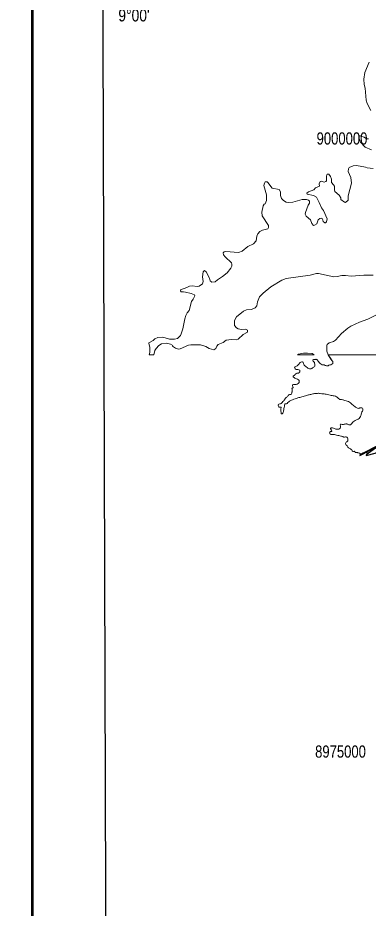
# Model space of a CAD drawing. Extents: x -1643653 to 4543381, y 1624270 to 13878484.
# Drawn here: x 559607 to 573973, y 8968607 to 9005087 of the extents above; entities that cross this region are included whole.
import ezdxf
from ezdxf.enums import TextEntityAlignment as Align

# ---------------------------------------------------------------- set-up
doc = ezdxf.new("R2010")
doc.units = 0
doc.header["$LTSCALE"] = 200
for name, color, linetype, lineweight in [('1', 7, 'Continuous', 13), ('25', 7, 'Continuous', 13), ('3', 7, 'Continuous', 13)]:
    doc.layers.add(name, color=color, linetype=linetype, lineweight=lineweight)
doc.layers.add('46', color=7, linetype='Continuous')
doc.layers.add('47', color=7, linetype='Continuous')

msp = doc.modelspace()

# ---------------------------------------------------------------- linework, layer by layer
at = {"layer": '1', "lineweight": 25}
msp.add_spline([(814781, 9009175.5), (814787.2, 9009173.4), (814796.9, 9009173.4), (814799.4, 9009172.4), (814805.1, 9009174.5), (814805.6, 9009176.5), (814811.7, 9009179.5), (814811.7, 9009179.5), (814801.5, 9009181), (814790.7, 9009181.5), (814784.1, 9009183.1), (814777.4, 9009185.1), (814778.4, 9009175.5)], degree=3, dxfattribs=at)
at = {"layer": '25'}
for p, q in [((571078.4, 8991274.5), (571756.4, 8991274.5)), ((572449.1, 8991100.5), (572334.3, 8991274.5))]:
    msp.add_line(p, q, dxfattribs=at)
at = {"layer": '25', "lineweight": 25}
for p, q in [((577877.7, 8989395.6), (573616.6, 8987168.4)), ((573625.3, 8987151.7), (577886.4, 8989378.8))]:
    msp.add_line(p, q, dxfattribs=at)
at = {"layer": '25'}
for points in [[(574014.7, 9003264.2), (573829.1, 9002845.8), (573792.1, 9002568.4), (573811.5, 9002356.8), (573854.8, 9002205), (573887.2, 9001708), (573923.9, 9001569.9), (574075.2, 9001284.5)], [(574014.7, 9003264.2), (573829.1, 9002845.8), (573792.1, 9002568.4), (573811.5, 9002356.8), (573854.8, 9002205), (573887.2, 9001708), (573923.9, 9001569.9), (574075.2, 9001284.5)], [(573989.5, 9000125.8), (573897.6, 9000125.8), (573807.4, 9000194.6), (573651.6, 9000255.2), (573610.4, 9000246.4), (573582.4, 9000173.4), (573662.4, 8999991.6), (573850.3, 8999788.5), (574105.5, 8999671.6)], [(573989.5, 9000125.8), (573897.6, 9000125.8), (573807.4, 9000194.6), (573651.6, 9000255.2), (573610.4, 9000246.4), (573582.4, 9000173.4), (573662.4, 8999991.6), (573850.3, 8999788.5), (574105.5, 8999671.6)], [(574169.9, 8998917.3), (573924.2, 8998943.1), (573861.2, 8998973.3), (573495.9, 8999038.2), (573357.6, 8999025.2), (573195.7, 8998954), (573160.9, 8998904.1), (573154.4, 8998796.3), (573264.6, 8998547.5), (573290.5, 8998318.6), (573147.9, 8997786.5), (573147.7, 8997610.4), (573041.5, 8997523.5), (573000.7, 8997531.6), (572856.3, 8997643.8), (572845.2, 8997713), (572780.5, 8997814.4), (572609.7, 8997966), (572588, 8998037.6), (572585.8, 8998184.3), (572553.4, 8998244.8), (572469.1, 8998340), (572464.8, 8998478.1), (572423.8, 8998581.8), (572354.7, 8998677), (572291.7, 8998674.9), (572271.2, 8998655.2), (572257.2, 8998599.6), (572268, 8998409.4), (572236.1, 8998375.1), (572164.3, 8998348.7), (572065.1, 8998398.3), (572002.4, 8998374.6), (571967.6, 8998284), (571974, 8998195.7), (571816.4, 8998119.6), (571747.1, 8998035.2), (571528.9, 8997959.6), (571454.6, 8997898.7), (571466.8, 8997864.9), (571737.3, 8997804.6), (571855.7, 8997734.5), (571967.5, 8997514.1), (572052.2, 8997299.3), (572136.7, 8997188.2), (572285.2, 8996857.2), (572259.3, 8996727.3), (572229.1, 8996686.3), (572195.3, 8996686.2), (572121.1, 8996746.8), (572103.5, 8996844.1), (572051.6, 8996874.3), (571987.6, 8996870.2), (571987.6, 8996870.2)], [(574169.9, 8998917.3), (573924.2, 8998943.1), (573861.2, 8998973.3), (573495.9, 8999038.2), (573357.6, 8999025.2), (573195.7, 8998954), (573160.9, 8998904.1), (573154.4, 8998796.3), (573264.6, 8998547.5), (573290.5, 8998318.6), (573147.9, 8997786.5), (573147.7, 8997610.4), (573041.5, 8997523.5), (573000.7, 8997531.6), (572856.3, 8997643.8), (572845.2, 8997713), (572780.5, 8997814.4), (572609.7, 8997966), (572588, 8998037.6), (572585.8, 8998184.3), (572553.4, 8998244.8), (572469.1, 8998340), (572464.8, 8998478.1), (572423.8, 8998581.8), (572354.7, 8998677), (572291.7, 8998674.9), (572271.2, 8998655.2), (572257.2, 8998599.6), (572268, 8998409.4), (572236.1, 8998375.1), (572164.3, 8998348.7), (572065.1, 8998398.3), (572002.4, 8998374.6), (571967.6, 8998284), (571974, 8998195.7), (571816.4, 8998119.6), (571747.1, 8998035.2), (571528.9, 8997959.6), (571454.6, 8997898.7), (571466.8, 8997864.9), (571737.3, 8997804.6), (571855.7, 8997734.5), (571967.5, 8997514.1), (572052.2, 8997299.3), (572136.7, 8997188.2), (572285.2, 8996857.2), (572259.3, 8996727.3), (572229.1, 8996686.3), (572195.3, 8996686.2), (572121.1, 8996746.8), (572103.5, 8996844.1), (572051.6, 8996874.3), (571987.6, 8996870.2)], [(571987.6, 8996870.2), (571926.5, 8996807.2), (571865.9, 8996647.3), (571765.8, 8996584.6), (571736.3, 8996582.5), (571667.1, 8996658.1), (571606.5, 8996815.9), (571427, 8996963.1), (571394.8, 8997042.6), (571399.2, 8997108.2), (571513.5, 8997414.5), (571561.1, 8997492.8), (571561.1, 8997570.3), (571528.4, 8997620.1), (571442, 8997643.9), (571269.3, 8997639.5), (570879.9, 8997529.3), (570707.2, 8997522.8), (570605.6, 8997535.8), (570495.4, 8997602.8), (570421.8, 8997687.3), (570378.7, 8997803.8), (570376.4, 8997959.5), (570326.5, 8998050.2), (570039.3, 8998110.8), (569862.2, 8998339.7), (569828.8, 8998363.9), (569747.5, 8998367.9), (569719.3, 8998318.1), (569695.6, 8998210), (569803.5, 8997832.4), (569805.7, 8997600.4), (569753.7, 8997466.5), (569708.6, 8997447), (569671.8, 8997384.4), (569607, 8997125.3), (569624.2, 8996969.4), (569883.5, 8996580.5), (569890, 8996489.7), (569862.1, 8996442.2), (569634.2, 8996387.6), (569524.8, 8996331.6), (569444.9, 8996241), (569401.6, 8996135.2), (569377.7, 8995955.6), (569276.2, 8995821.7), (569042.7, 8995719.9), (568806.8, 8995531.7), (568653.5, 8995475.6), (568134.7, 8995512.3), (568072.2, 8995501.6), (568030.8, 8995462.5), (568041.7, 8995378.5), (568108.6, 8995287.8), (568364, 8995043), (568387.6, 8994997.6), (568385.5, 8994911.7), (568342.3, 8994825.1), (568190.7, 8994643.1), (567996.1, 8994487.5), (567788.8, 8994357.9), (567698, 8994275.9), (567560, 8994252.1), (567499.2, 8994304.1), (567462.2, 8994418.7), (567330.6, 8994677.7), (567263.6, 8994734), (567200.7, 8994675.1), (567183.6, 8994478), (567209.4, 8994288.5), (567174.9, 8994185.2), (567041.5, 8994087.6), (566962.8, 8994081.3), (566755.8, 8994109.3), (566652.7, 8994094.4), (566443.9, 8994001.2), (566287.2, 8993950.5), (566277.5, 8993895.3), (566309.1, 8993863.6), (566406.3, 8993853.8)], [(571987.6, 8996870.2), (571926.5, 8996807.2), (571865.9, 8996647.3), (571765.8, 8996584.6), (571736.3, 8996582.5), (571667.1, 8996658.1), (571606.5, 8996815.9), (571427, 8996963.1), (571394.8, 8997042.6), (571399.2, 8997108.2), (571513.5, 8997414.5), (571561.1, 8997492.8), (571561.1, 8997570.3), (571528.4, 8997620.1), (571442, 8997643.9), (571269.3, 8997639.5), (570879.9, 8997529.3), (570707.2, 8997522.8), (570605.6, 8997535.8), (570495.4, 8997602.8), (570421.8, 8997687.3), (570378.7, 8997803.8), (570376.4, 8997959.5), (570326.5, 8998050.2), (570039.3, 8998110.8), (569862.2, 8998339.7), (569828.8, 8998363.9), (569747.5, 8998367.9), (569719.3, 8998318.1), (569695.6, 8998210), (569803.5, 8997832.4), (569805.7, 8997600.4), (569753.7, 8997466.5), (569708.6, 8997447), (569671.8, 8997384.4), (569607, 8997125.3), (569624.2, 8996969.4), (569883.5, 8996580.5), (569890, 8996489.7), (569862.1, 8996442.2), (569634.2, 8996387.6), (569524.8, 8996331.6), (569444.9, 8996241), (569401.6, 8996135.2), (569377.7, 8995955.6), (569276.2, 8995821.7), (569042.7, 8995719.9), (568806.8, 8995531.7), (568653.5, 8995475.6), (568134.7, 8995512.3), (568072.2, 8995501.6), (568030.8, 8995462.5), (568041.7, 8995378.5), (568108.6, 8995287.8), (568364, 8995043), (568387.6, 8994997.6), (568385.5, 8994911.7), (568342.3, 8994825.1), (568190.7, 8994643.1), (567996.1, 8994487.5), (567788.8, 8994357.9), (567698, 8994275.9), (567560, 8994252.1), (567499.2, 8994304.1), (567462.2, 8994418.7), (567330.6, 8994677.7), (567263.6, 8994734), (567200.7, 8994675.1), (567183.6, 8994478), (567209.4, 8994288.5), (567174.9, 8994185.2), (567041.5, 8994087.6), (566962.8, 8994081.3), (566755.8, 8994109.3), (566652.7, 8994094.4), (566443.9, 8994001.2), (566287.2, 8993950.5), (566277.5, 8993895.3), (566309.1, 8993863.6), (566406.3, 8993853.8)], [(568487.1, 8992684.5), (568569.1, 8992838), (568854.8, 8993074), (568977.6, 8993117), (569194, 8993136.6), (569341.2, 8993199.5), (569413.7, 8993286.4), (569438.4, 8993446), (569516.9, 8993653.7), (569666.9, 8993803.6), (569976.6, 8994064), (570432.9, 8994338.6), (570607.5, 8994403.3), (571593.3, 8994539.5), (571853, 8994615.2), (571939.4, 8994608.7), (572566.4, 8994472.6), (572704.5, 8994483.3), (572894.9, 8994524.4), (573037.9, 8994528.7), (573275.2, 8994507.1), (573798.6, 8994543.9), (574179, 8994537.4)], [(568487.1, 8992684.5), (568569.1, 8992838), (568854.8, 8993074), (568977.6, 8993117), (569194, 8993136.6), (569341.2, 8993199.5), (569413.7, 8993286.4), (569438.4, 8993446), (569516.9, 8993653.7), (569666.9, 8993803.6), (569976.6, 8994064), (570432.9, 8994338.6), (570607.5, 8994403.3), (571593.3, 8994539.5), (571853, 8994615.2), (571939.4, 8994608.7), (572566.4, 8994472.6), (572704.5, 8994483.3), (572894.9, 8994524.4), (573037.9, 8994528.7), (573275.2, 8994507.1), (573798.6, 8994543.9), (574179, 8994537.4)], [(566406.3, 8993853.8), (566487.5, 8993845.6), (566720.4, 8993798.2), (566856.8, 8993741.9), (566861.3, 8993701.1), (566803.3, 8993560.8), (566725.3, 8993467.3), (566628, 8993095.8), (566556.6, 8993002.5), (566500.5, 8992892.5), (566452.8, 8992749.4), (566371.7, 8992344.8), (566307.9, 8992133.6), (566273.3, 8992070.6), (566159, 8991941.3), (566037.8, 8991923.8), (565822.3, 8991921.6), (565557.9, 8992003.8), (565347.2, 8991985.1), (565224.8, 8991932.3), (565151.5, 8991872), (564980.8, 8991770.3), (564976.4, 8991740.3), (564976.4, 8991740.3), (565017.4, 8991591.1), (565017.4, 8991374.7), (564994.9, 8991274.5), (565186.5, 8991274.5)], [(566406.3, 8993853.8), (566487.5, 8993845.6), (566720.4, 8993798.2), (566856.8, 8993741.9), (566861.3, 8993701.1), (566803.3, 8993560.8), (566725.3, 8993467.3), (566628, 8993095.8), (566556.6, 8993002.5), (566500.5, 8992892.5), (566452.8, 8992749.4), (566371.7, 8992344.8), (566307.9, 8992133.6), (566273.3, 8992070.6), (566159, 8991941.3), (566037.8, 8991923.8), (565822.3, 8991921.6), (565557.9, 8992003.8), (565347.2, 8991985.1), (565224.8, 8991932.3), (565151.5, 8991872), (564980.8, 8991770.3), (564976.4, 8991740.3), (564976.4, 8991740.3), (565017.4, 8991591.1), (565017.4, 8991374.7), (564994.9, 8991274.5), (565186.5, 8991274.5)], [(574604.9, 8993095.5), (574470.8, 8992998.2), (573958.5, 8992743.1), (573612.4, 8992613.3), (573265.1, 8992456.7), (573136.5, 8992373), (572873.3, 8992152.9), (572626.3, 8991880.2), (572549.3, 8991828.8), (572375.9, 8991770.2), (572289.7, 8991707.6), (572272.4, 8991674.5), (572272.4, 8991435), (572334.3, 8991274.5), (578446.9, 8991274.5)], [(574604.9, 8993095.5), (574470.8, 8992998.2), (573958.5, 8992743.1), (573612.4, 8992613.3), (573265.1, 8992456.7), (573136.5, 8992373), (572873.3, 8992152.9), (572626.3, 8991880.2), (572549.3, 8991828.8), (572375.9, 8991770.2), (572289.7, 8991707.6), (572272.4, 8991674.5), (572272.4, 8991435), (572334.3, 8991274.5)], [(565186.5, 8991274.5), (565229.4, 8991456.8), (565277, 8991543.6), (565385, 8991662.2), (565495.2, 8991724.9), (565699.6, 8991750.3), (565868.8, 8991714.1), (565962.8, 8991656.3), (565956, 8991638.4), (566069.6, 8991550.2), (566202.1, 8991510.9), (566262.2, 8991518.1), (566602.6, 8991670.9), (566699.3, 8991686), (567101.1, 8991683.8), (567313.2, 8991623.3), (567457.9, 8991543.5), (567647.8, 8991487.2), (567719.8, 8991534.9), (567767.4, 8991634.3), (567827.8, 8991705.4), (568027.3, 8991790.1), (568156.3, 8991874), (568371.7, 8991906.5), (568571.6, 8991889.4), (568638.4, 8991921.7), (568847.5, 8992104.9), (569018.9, 8992209.7), (569025.4, 8992289.9), (568938.9, 8992336.7), (568783.5, 8992319.5), (568643, 8992349.7), (568576.9, 8992385), (568495.8, 8992479.4), (568487.1, 8992684.5)], [(565186.5, 8991274.5), (565229.4, 8991456.8), (565277, 8991543.6), (565385, 8991662.2), (565495.2, 8991724.9), (565699.6, 8991750.3), (565868.8, 8991714.1), (565962.8, 8991656.3), (565956, 8991638.4), (566069.6, 8991550.2), (566202.1, 8991510.9), (566262.2, 8991518.1), (566602.6, 8991670.9), (566699.3, 8991686), (567101.1, 8991683.8), (567313.2, 8991623.3), (567457.9, 8991543.5), (567647.8, 8991487.2), (567719.8, 8991534.9), (567767.4, 8991634.3), (567827.8, 8991705.4), (568027.3, 8991790.1), (568156.3, 8991874), (568371.7, 8991906.5), (568571.6, 8991889.4), (568638.4, 8991921.7), (568847.5, 8992104.9), (569018.9, 8992209.7), (569025.4, 8992289.9), (568938.9, 8992336.7), (568783.5, 8992319.5), (568643, 8992349.7), (568576.9, 8992385), (568495.8, 8992479.4), (568487.1, 8992684.5)], [(571756.4, 8991274.5), (571671.1, 8991329.3), (571489.6, 8991346.6), (571316.8, 8991342.2), (571109.2, 8991305.4), (571078.4, 8991274.5)], [(571756.4, 8991274.5), (571671.1, 8991329.3), (571489.6, 8991346.6), (571316.8, 8991342.2), (571109.2, 8991305.4), (571078.4, 8991274.5)], [(578351.6, 8991043.2), (578446.9, 8991274.5), (572334.3, 8991274.5), (572447.3, 8991102.9), (572499.8, 8991033.9)], [(573946.4, 8987228.8), (575651.3, 8988475.2), (578012.7, 8989366.8), (578009.5, 8989418.3)]]:
    msp.add_lwpolyline(points, dxfattribs=at)
at = {"layer": '25', "lineweight": 25}
for points in [[(578012.9, 8989352.9), (577187, 8989042.7), (576324, 8988712.7), (575950.1, 8988578.7), (575647.5, 8988463.9), (575187.8, 8988130.1), (574877.2, 8987905.3), (574268.6, 8987457.2), (573884, 8987175.6)], [(573895.3, 8987154), (574263.9, 8987244.7), (575107.4, 8987587), (575919.3, 8987877.8), (576674.3, 8988291.2), (577269.1, 8988857.9), (578024.2, 8989331.3)]]:
    msp.add_lwpolyline(points, dxfattribs=at)
at = {"layer": '25'}
for points in [[(572497.9, 8989611.9), (572416.1, 8989621.7), (572298.7, 8989654.1), (572210.5, 8989666.4), (572124.8, 8989681.2), (572006.5, 8989692.2), (571934.7, 8989703.3), (571895.8, 8989700.6), (571733.8, 8989683.8), (571587.2, 8989646.9), (571453.1, 8989617.6), (571351.8, 8989579.6), (571165.1, 8989536.3), (571023.7, 8989489.3), (570824.7, 8989420.8), (570717.5, 8989353.9), (570650.5, 8989289.6), (570581.7, 8989265.5), (570557.9, 8989261.6), (570536.5, 8989171.1), (570516.3, 8989080.5), (570500.1, 8988981.1), (570490.7, 8988932), (570480, 8988888), (570410, 8988857.6), (570400.3, 8988925.5), (570389.6, 8989066.3), (570400.3, 8989105.3), (570401.2, 8989131.7), (570339.7, 8989129), (570310.5, 8989145.2), (570285.9, 8989198), (570293, 8989230.7), (570411.6, 8989290.1), (570477.3, 8989360.7), (570556.4, 8989461.5), (570612, 8989532.1), (570692.7, 8989609.1), (570714.8, 8989641.8), (570783.9, 8989649.6), (570828.7, 8989677.3), (570845.5, 8989742.8), (570853.5, 8989794.3), (570853.3, 8989809.4), (570852.4, 8989877.3), (570850.7, 8989910), (570881.9, 8989923.9), (570867.7, 8990045.8), (570873.8, 8990055.9), (570956.8, 8990057.4), (571136.7, 8990140.9), (571138, 8990227.7), (571073.1, 8990284.1), (570988.5, 8990315.2), (570949.2, 8990336.5), (570913.7, 8990362.8), (570894.5, 8990381.6), (570910.4, 8990415.6), (570967.7, 8990454.8), (571009.8, 8990502.7), (571044.6, 8990531.7), (571122.5, 8990533.2), (571168.4, 8990581.1), (571168.7, 8990652.7), (571082.9, 8990673.9), (570973, 8990711.2), (570957.2, 8990759), (571030.7, 8990809.5), (571089.2, 8990854.9), (571136.3, 8990904.1), (571180.8, 8990962.1), (571302.4, 8990981.3), (571318.4, 8990918.5), (571353.3, 8990850.7), (571399, 8990815.6), (571537.4, 8990716.7), (571595.4, 8990703), (571610.5, 8990704.3), (571630.6, 8990706.9), (571685.4, 8990741), (571779.9, 8990818), (571783.9, 8990893.5), (571765.3, 8990965.1), (571729.5, 8991007.7), (571709, 8991040.3), (571707.2, 8991075.5), (571765, 8991082), (571805.2, 8991084.6), (571839, 8991094.8), (571888.5, 8991059.7), (571937, 8991003.3)], [(571937, 8991003.3), (571888.5, 8991059.7), (571839, 8991094.8), (571805.2, 8991084.6), (571765, 8991082), (571707.2, 8991075.5), (571709, 8991040.3), (571729.5, 8991007.7), (571765.3, 8990965.1), (571783.9, 8990893.5), (571779.9, 8990818), (571685.4, 8990741), (571630.6, 8990706.9), (571610.5, 8990704.3), (571595.4, 8990703), (571537.4, 8990716.7), (571399, 8990815.6), (571353.3, 8990850.7), (571318.4, 8990918.5), (571302.4, 8990981.3), (571180.8, 8990962.1), (571136.3, 8990904.1), (571089.2, 8990854.9), (571030.7, 8990809.5), (570957.2, 8990759), (570973, 8990711.2), (571082.9, 8990673.9), (571168.7, 8990652.7), (571168.4, 8990581.1), (571122.5, 8990533.2), (571044.6, 8990531.7), (571009.8, 8990502.7), (570967.7, 8990454.8), (570910.4, 8990415.6), (570894.5, 8990381.6), (570913.7, 8990362.8), (570949.2, 8990336.5), (570988.5, 8990315.2), (571073.1, 8990284.1), (571138, 8990227.7), (571136.7, 8990140.9), (570956.8, 8990057.4), (570873.8, 8990055.9), (570867.7, 8990045.8), (570881.9, 8989923.9), (570850.7, 8989910), (570852.4, 8989877.3), (570853.3, 8989809.4), (570853.5, 8989794.3), (570845.5, 8989742.8), (570828.7, 8989677.3), (570783.9, 8989649.6), (570714.8, 8989641.8), (570692.7, 8989609.1), (570612, 8989532.1), (570556.4, 8989461.5), (570477.3, 8989360.7), (570411.6, 8989290.1), (570293, 8989230.7), (570285.9, 8989198), (570310.5, 8989145.2), (570339.7, 8989129), (570401.2, 8989131.7), (570400.3, 8989105.3), (570389.6, 8989066.3), (570400.3, 8988925.5), (570410, 8988857.6), (570480, 8988888), (570490.7, 8988932), (570500.1, 8988981.1), (570516.3, 8989080.5), (570536.5, 8989171.1), (570557.9, 8989261.6), (570581.7, 8989265.5), (570650.5, 8989289.6), (570717.5, 8989353.9), (570824.7, 8989420.8), (571023.7, 8989489.3), (571165.1, 8989536.3), (571351.8, 8989579.6), (571453.1, 8989617.6), (571587.2, 8989646.9), (571733.8, 8989683.8), (571895.8, 8989700.6), (571934.7, 8989703.3), (572006.5, 8989692.2), (572124.8, 8989681.2), (572210.5, 8989666.4), (572298.7, 8989654.1), (572416.1, 8989621.7), (572497.9, 8989611.9)], [(571937, 8991003.3), (571999.7, 8990925.5), (572088.4, 8990874.2), (572123.6, 8990870.6), (572210.7, 8990848.2), (572263.8, 8990825.7), (572337.9, 8990833.5), (572365.3, 8990852.4), (572440.4, 8990872.8), (572520.2, 8990924.6), (572529.6, 8990971.1), (572499.8, 8991033.9), (572447.3, 8991102.9)], [(572499.8, 8991033.9), (572529.6, 8990971.1), (572520.2, 8990924.6), (572440.4, 8990872.8), (572365.3, 8990852.4), (572337.9, 8990833.5), (572263.8, 8990825.7), (572210.7, 8990848.2), (572123.6, 8990870.6), (572088.4, 8990874.2), (571999.7, 8990925.5), (571937, 8991003.3)], [(573946.4, 8987228.8), (573942.2, 8987251.7), (573936.8, 8987263.8), (573898.8, 8987282.6), (573768.4, 8987263.3), (573732.2, 8987244.3), (573693.6, 8987217.8), (573613.9, 8987252.8), (573547, 8987267.7), (573515.4, 8987281.4), (573456.3, 8987280), (573433.3, 8987308.8), (573396.6, 8987326.3), (573352.8, 8987317.4), (573295.3, 8987380.1), (573196.2, 8987457.7), (573136.6, 8987497.8), (573112, 8987549.3), (573058.6, 8987593.1), (573066, 8987695), (573128.2, 8987739.2), (573142.9, 8987771.9), (573142.1, 8987824.7), (573143.3, 8987828.5), (573127.6, 8987875), (573074.2, 8987920.1), (573005.3, 8987906), (572963.7, 8987908.4), (572949.8, 8987918.4), (572918.1, 8987935.9), (572845, 8987947), (572768.1, 8987966.9), (572676, 8987988), (572591.5, 8988009.2), (572499.7, 8988011.4), (572436.8, 8988013.7), (572394.6, 8988063.9), (572384.2, 8988087.7), (572423.8, 8988133.1), (572476.6, 8988138.3), (572468.4, 8988187.3), (572436.4, 8988230), (572432.1, 8988263.9), (572503.4, 8988290.5), (572590.6, 8988256.8), (572705.4, 8988228.2), (572769.5, 8988232.2), (572826.8, 8988271.4), (572840.8, 8988346.8), (572828.9, 8988392.1), (572838.4, 8988434.8), (572907.7, 8988423.7), (572962.9, 8988427.7), (572999.2, 8988440.3), (573054.4, 8988445.5), (573062, 8988445.6), (573097.2, 8988446.9), (573126.2, 8988438.2), (573178.1, 8988415.7), (573242.3, 8988407.1), (573299.2, 8988471.4), (573362.5, 8988535.7), (573437.2, 8988588.7), (573487.1, 8988616.6), (573563.4, 8988645.7), (573631.6, 8988710), (573673.3, 8988791.9), (573687.5, 8988852.3), (573707.9, 8988926.5), (573725.1, 8988953), (573737.5, 8988965.6), (573746.2, 8989062.4), (573713, 8989103.8), (573653.9, 8989102.3), (573613.8, 8989097.2), (573561.1, 8989084.5), (573511.7, 8989113.2), (573458.6, 8989135.7), (573420.6, 8989157), (573288.3, 8989273.5), (573248.8, 8989308.6), (573161.3, 8989363.7), (573065.3, 8989393.6), (572971.9, 8989424.7), (572928.9, 8989440.9), (572833.3, 8989444.4), (572790.3, 8989463.1), (572725.5, 8989513.2), (572673.4, 8989559.6), (572582.4, 8989592), (572497.9, 8989611.9)], [(572497.9, 8989611.9), (572582.4, 8989592), (572673.4, 8989559.6), (572725.5, 8989513.2), (572790.3, 8989463.1), (572833.3, 8989444.4), (572928.9, 8989440.9), (572971.9, 8989424.7), (573065.3, 8989393.6), (573161.3, 8989363.7), (573248.8, 8989308.6), (573288.3, 8989273.5), (573420.6, 8989157), (573458.6, 8989135.7), (573511.7, 8989113.2), (573561.1, 8989084.5), (573613.8, 8989097.2), (573653.9, 8989102.3), (573713, 8989103.8), (573746.2, 8989062.4), (573737.5, 8988965.6), (573725.1, 8988953), (573707.9, 8988926.5), (573687.5, 8988852.3), (573673.3, 8988791.9), (573631.6, 8988710), (573563.4, 8988645.7), (573487.1, 8988616.6), (573437.2, 8988588.7), (573362.5, 8988535.7), (573299.2, 8988471.4), (573242.3, 8988407.1), (573178.1, 8988415.7), (573126.2, 8988438.2), (573097.2, 8988446.9), (573062, 8988445.6), (573054.4, 8988445.5), (572999.2, 8988440.3), (572962.9, 8988427.7), (572907.7, 8988423.7), (572838.4, 8988434.8), (572828.9, 8988392.1), (572840.8, 8988346.8), (572826.8, 8988271.4), (572769.5, 8988232.2), (572705.4, 8988228.2), (572590.6, 8988256.8), (572503.4, 8988290.5), (572432.1, 8988263.9), (572436.4, 8988230), (572468.4, 8988187.3), (572476.6, 8988138.3), (572423.8, 8988133.1), (572384.2, 8988087.7), (572394.6, 8988063.9), (572436.8, 8988013.7), (572499.7, 8988011.4)], [(572499.7, 8988011.4), (572591.5, 8988009.2), (572676, 8987988), (572768.1, 8987966.9), (572845, 8987947), (572918.1, 8987935.9), (572949.8, 8987918.4), (572963.7, 8987908.4), (573005.3, 8987906), (573074.2, 8987920.1), (573127.6, 8987875), (573143.3, 8987828.5), (573142.1, 8987824.7), (573142.9, 8987771.9), (573128.2, 8987739.2), (573066, 8987695), (573058.6, 8987593.1), (573112, 8987549.3), (573136.6, 8987497.8), (573196.2, 8987457.7), (573295.3, 8987380.1)], [(573295.3, 8987380.1), (573352.8, 8987317.4), (573396.6, 8987326.3), (573433.3, 8987308.8), (573456.3, 8987280), (573515.4, 8987281.4), (573547, 8987267.7), (573613.9, 8987252.8), (573693.6, 8987217.8), (573732.2, 8987244.3), (573768.4, 8987263.3), (573898.8, 8987282.6), (573936.8, 8987263.8), (573942.2, 8987251.7), (573946.4, 8987228.8)]]:
    msp.add_spline(points, degree=3, dxfattribs=at)
at = {"layer": '3', "lineweight": 53}
msp.add_lwpolyline([(840307.3, 9029887.8), (840307.3, 8886387.8), (560211.7, 8886387.8), (560211.7, 9029887.8)], close=True, dxfattribs=at)
msp.add_lwpolyline([(840307.3, 9029887.8), (840307.3, 8886387.8), (560211.7, 8886387.8), (560211.7, 9029887.8)], close=True, dxfattribs=at)
at = {"layer": '3', "lineweight": 25}
msp.add_lwpolyline([(563033.9, 9026438.8), (793061.1, 9026438.8), (793495.6, 8889836.8), (563468.3, 8889836.8)], close=True, dxfattribs=at)

# ---------------------------------------------------------------- texts
at = {"layer": '46', "width": 0.85}
msp.add_text("9°00'", height=500, dxfattribs=at).set_placement((564370.9, 9004939.3), align=Align.CENTER)
at = {"layer": '47', "width": 0.8}
for s, p in [('9000000', (572898.5, 8999894)), ('8975000', (572837.8, 8974774.3))]:
    msp.add_text(s, height=500, dxfattribs=at).set_placement(p, align=Align.CENTER)

doc.saveas('drawing.dxf')
